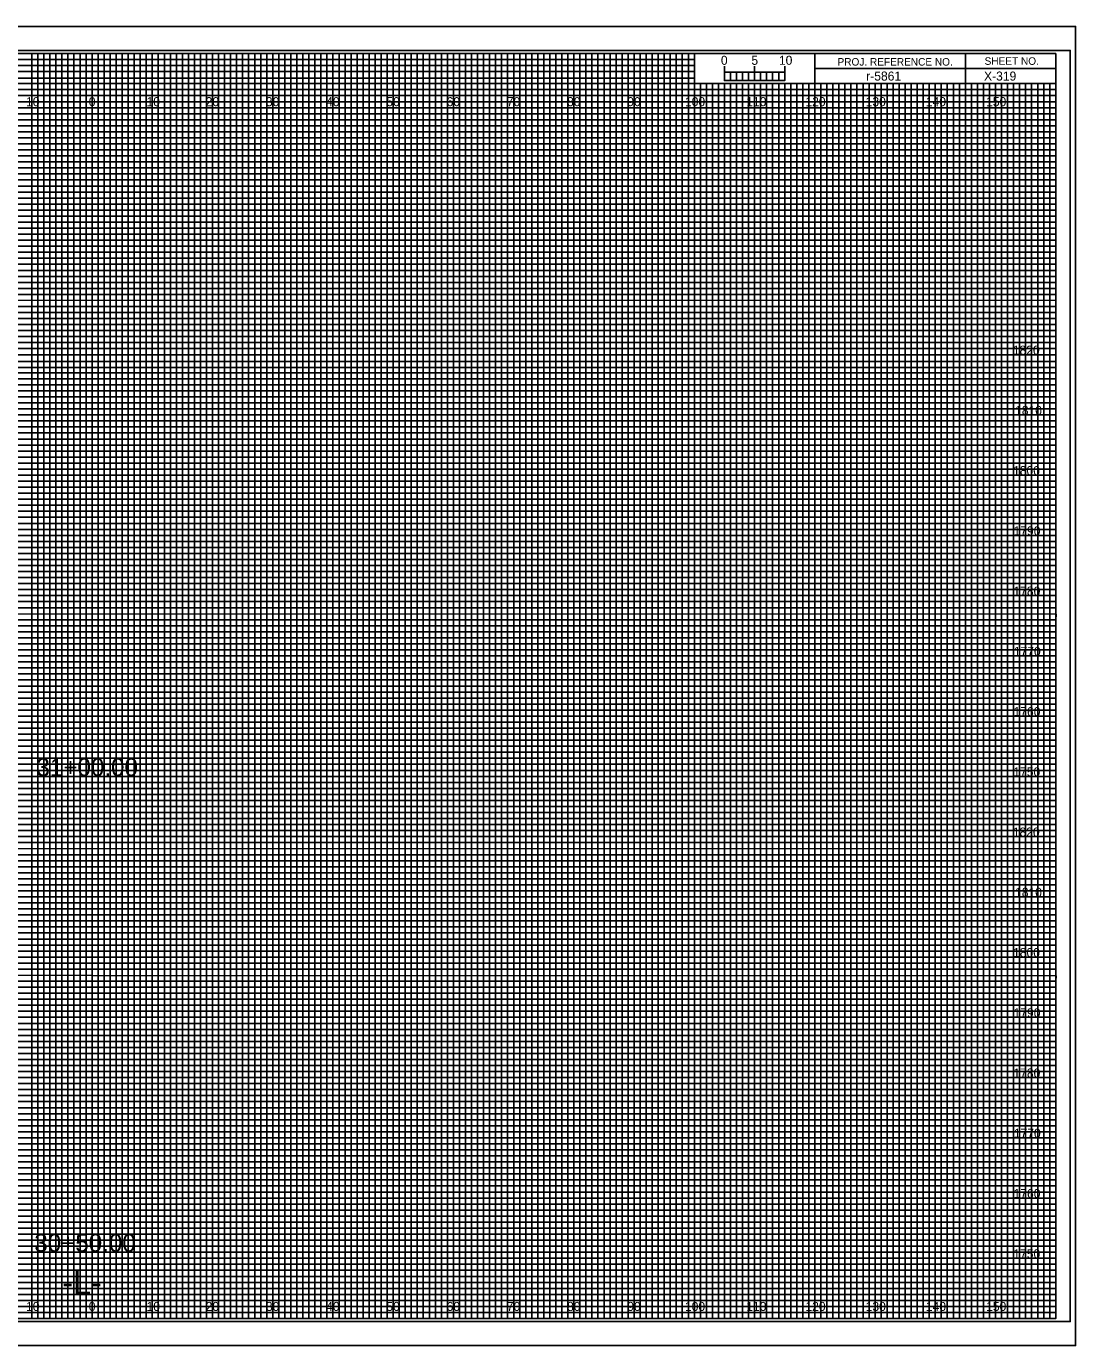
# Model space of a CAD drawing. Extents: x -15 to 323, y -5 to 6170.
# Drawn here: x 149.1 to 323.3, y 3295.5 to 3514.5 of the extents above; entities that cross this region are included whole.
import ezdxf

# ---------------------------------------------------------------- set-up
doc = ezdxf.new("R2010")
doc.units = 0
for name, color, linetype in [('Prop XS Alignment Label', 7, 'Continuous'), ('Prop XS Bar Scale Labels', 7, 'Continuous'), ('Prop XS DDE', 7, 'Continuous'), ('Prop XS DDE Earthwork Shape', 7, 'Continuous'), ('Prop XS DDE Slope Text', 7, 'Continuous'), ('Prop XS DDE Text', 7, 'Continuous'), ('Prop XS Earthwork Shape', 7, 'Continuous'), ('Prop XS Noise Wall', 7, 'Continuous'), ('Prop XS Project Number', 7, 'Continuous'), ('Prop XS Retaining Wall', 7, 'Continuous'), ('Prop XS Station Labels', 7, 'Continuous'), ('Prop XS Temporary Shoring', 7, 'Continuous'), ('Scratch_Level_3', 7, 'Continuous'), ('Scratch_Level_7', 7, 'Continuous'), ('Scratch_Level_8', 7, 'Continuous'), ('Sheet Cross Section Grid Minor 1 CELL', 7, 'Continuous')]:
    doc.layers.add(name, color=color, linetype=linetype)

msp = doc.modelspace()

# ---------------------------------------------------------------- linework, layer by layer
at = {"layer": 'Prop XS Alignment Label'}
for p, q in [((265, 3505.49), (265, 3507.9)), ((265, 3506.9), (265, 3507.9)), ((270, 3505.49), (270, 3507.9)), ((275, 3505.49), (275, 3507.9)), ((275, 3506.9), (275, 3507.9))]:
    msp.add_line(p, q, dxfattribs=at)
for points in [[(275, 3506.9), (265, 3506.9), (265, 3505.49), (275, 3505.49)], [(265, 3506.9), (266, 3506.9), (266, 3505.49), (265, 3505.49)], [(267, 3506.9), (268, 3506.9), (268, 3505.49), (267, 3505.49)], [(269, 3506.9), (270, 3506.9), (270, 3505.49), (269, 3505.49)], [(271, 3506.9), (272, 3506.9), (272, 3505.49), (271, 3505.49)], [(273, 3506.9), (274, 3506.9), (274, 3505.49), (273, 3505.49)]]:
    msp.add_lwpolyline(points, close=True, dxfattribs=at)
at = {"layer": 'Prop XS DDE'}
msp.add_lwpolyline([(-13.4, 3295.5), (323.3, 3295.5), (323.3, 3514.5), (-13.4, 3514.5)], close=True, dxfattribs=at)
at = {"layer": 'Prop XS DDE Slope Text'}
msp.add_lwpolyline([(-10.8, 3299.5), (322.4, 3299.5), (322.4, 3510.5), (-10.8, 3510.5)], close=True, dxfattribs=at)
at = {"layer": 'Prop XS DDE Text'}
for p, q in [((150, 3300), (150, 3510)), ((160, 3300), (160, 3510)), ((170, 3300), (170, 3510)), ((180, 3300), (180, 3510)), ((190, 3300), (190, 3510)), ((200, 3300), (200, 3510)), ((210, 3300), (210, 3510)), ((220, 3300), (220, 3510)), ((230, 3300), (230, 3510)), ((240, 3300), (240, 3510)), ((250, 3300), (250, 3510)), ((260, 3300), (260, 3504.69)), ((270, 3300), (270, 3504.69)), ((280, 3300), (280, 3504.69)), ((290, 3300), (290, 3504.69)), ((300, 3300), (300, 3504.69)), ((310, 3300), (310, 3504.69)), ((0, 3500), (320, 3500)), ((0, 3490), (320, 3490)), ((0, 3480), (320, 3480)), ((0, 3470), (320, 3470)), ((0, 3460), (320, 3460)), ((0, 3450), (320, 3450)), ((0, 3440), (320, 3440)), ((0, 3430), (320, 3430)), ((0, 3420), (320, 3420)), ((0, 3410), (320, 3410)), ((0, 3400), (320, 3400)), ((0, 3390), (320, 3390)), ((0, 3380), (320, 3380)), ((0, 3370), (320, 3370)), ((0, 3360), (320, 3360)), ((0, 3350), (320, 3350)), ((0, 3340), (320, 3340)), ((0, 3330), (320, 3330)), ((0, 3320), (320, 3320)), ((0, 3310), (320, 3310))]:
    msp.add_line(p, q, dxfattribs=at)
at = {"layer": 'Prop XS Earthwork Shape'}
for p, q in [((150, 3510), (140, 3510)), ((150, 3300), (150, 3510)), ((170, 3510), (160, 3510)), ((160, 3510), (160, 3300)), ((170, 3300), (170, 3510)), ((190, 3510), (180, 3510)), ((180, 3510), (180, 3300)), ((190, 3300), (190, 3510)), ((210, 3510), (200, 3510)), ((200, 3510), (200, 3300)), ((210, 3300), (210, 3510)), ((230, 3510), (220, 3510)), ((220, 3510), (220, 3300)), ((230, 3300), (230, 3510)), ((250, 3510), (240, 3510)), ((240, 3510), (240, 3300)), ((250, 3300), (250, 3510)), ((260, 3510), (260, 3300)), ((270, 3300), (270, 3505)), ((290, 3505), (280, 3505)), ((280, 3505), (280, 3300)), ((290, 3300), (290, 3505)), ((310, 3505), (300, 3505)), ((300, 3505), (300, 3300)), ((310, 3300), (310, 3505)), ((160, 3300), (150, 3300)), ((180, 3300), (170, 3300)), ((200, 3300), (190, 3300)), ((220, 3300), (210, 3300)), ((240, 3300), (230, 3300)), ((260, 3300), (250, 3300)), ((280, 3300), (270, 3300)), ((300, 3300), (290, 3300)), ((320, 3300), (310, 3300)), ((320, 3300), (320, 3300))]:
    msp.add_line(p, q, dxfattribs=at)
for points in [[(0, 3500), (320, 3500), (320, 3490), (0, 3490)], [(0, 3480), (320, 3480), (320, 3470), (0, 3470)], [(0, 3460), (320, 3460), (320, 3450), (0, 3450)], [(0, 3440), (320, 3440), (320, 3430), (0, 3430)], [(0, 3420), (320, 3420), (320, 3410), (0, 3410)], [(0, 3400), (320, 3400), (320, 3390), (0, 3390)], [(0, 3380), (320, 3380), (320, 3370), (0, 3370)], [(0, 3360), (320, 3360), (320, 3350), (0, 3350)], [(0, 3340), (320, 3340), (320, 3330), (0, 3330)], [(0, 3320), (320, 3320), (320, 3310), (0, 3310)]]:
    msp.add_lwpolyline(points, dxfattribs=at)
at = {"layer": 'Prop XS Noise Wall'}
for p, q in [((305, 3510), (305, 3505)), ((305, 3505), (305, 3510)), ((280, 3507.5), (280, 3505)), ((320, 3507.49), (280, 3507.49)), ((280, 3505), (320, 3505))]:
    msp.add_line(p, q, dxfattribs=at)
for points in [[(320, 3510), (0, 3510), (0, 3300), (320, 3300)], [(280, 3510), (260, 3510), (260, 3505.03), (280, 3505.03)], [(320, 3510), (280, 3510), (280, 3505), (320, 3505)]]:
    msp.add_lwpolyline(points, close=True, dxfattribs=at)
at = {"layer": 'Prop XS Retaining Wall'}
for p, q in [((267, 3505), (266.01, 3505)), ((266.01, 3505), (266.01, 3300)), ((267, 3300), (267, 3505)), ((269, 3505), (268, 3505)), ((268, 3505), (268, 3300)), ((269, 3300), (269, 3505)), ((266.01, 3300), (265, 3300)), ((268, 3300), (267, 3300))]:
    msp.add_line(p, q, dxfattribs=at)
for points in [[(150, 3300), (151, 3300), (151, 3510), (152, 3510), (152, 3300)], [(152, 3300), (153, 3300), (153, 3510), (154, 3510), (154, 3300)], [(155, 3300), (156, 3300), (156, 3510), (157, 3510), (157, 3300)], [(157, 3300), (158, 3300), (158, 3510), (159, 3510), (159, 3300)], [(160, 3300), (161, 3300), (161, 3510), (162, 3510), (162, 3300)], [(162, 3300), (163, 3300), (163, 3510), (164, 3510), (164, 3300)], [(165, 3300), (166, 3300), (166, 3510), (167, 3510), (167, 3300)], [(167, 3300), (168, 3300), (168, 3510), (169, 3510), (169, 3300)], [(170, 3300), (171, 3300), (171, 3510), (172, 3510), (172, 3300)], [(172, 3300), (173, 3300), (173, 3510), (174, 3510), (174, 3300)], [(175, 3300), (176, 3300), (176, 3510), (177, 3510), (177, 3300)], [(177, 3300), (178, 3300), (178, 3510), (179, 3510), (179, 3300)], [(180, 3300), (181, 3300), (181, 3510), (182, 3510), (182, 3300)], [(182, 3300), (183, 3300), (183, 3510), (184, 3510), (184, 3300)], [(185, 3300), (186, 3300), (186, 3510), (187, 3510), (187, 3300)], [(187, 3300), (188, 3300), (188, 3510), (189, 3510), (189, 3300)], [(190, 3300), (191, 3300), (191, 3510), (192, 3510), (192, 3300)], [(192, 3300), (193, 3300), (193, 3510), (194, 3510), (194, 3300)], [(195, 3300), (196, 3300), (196, 3510), (197, 3510), (197, 3300)], [(197, 3300), (198, 3300), (198, 3510), (199, 3510), (199, 3300)], [(200, 3300), (201, 3300), (201, 3510), (202, 3510), (202, 3300)], [(202, 3300), (203, 3300), (203, 3510), (204, 3510), (204, 3300)], [(205, 3300), (206, 3300), (206, 3510), (207, 3510), (207, 3300)], [(207, 3300), (208, 3300), (208, 3510), (209, 3510), (209, 3300)], [(210, 3300), (211, 3300), (211, 3510), (212, 3510), (212, 3300)], [(212, 3300), (213, 3300), (213, 3510), (214, 3510), (214, 3300)], [(215, 3300), (216, 3300), (216, 3510), (217, 3510), (217, 3300)], [(217, 3300), (218, 3300), (218, 3510), (219, 3510), (219, 3300)], [(220, 3300), (221, 3300), (221, 3510), (222, 3510), (222, 3300)], [(222, 3300), (223, 3300), (223, 3510), (224, 3510), (224, 3300)], [(225, 3300), (226, 3300), (226, 3510), (227, 3510), (227, 3300)], [(227, 3300), (228, 3300), (228, 3510), (229, 3510), (229, 3300)], [(230, 3300), (231, 3300), (231, 3510), (232, 3510), (232, 3300)], [(232, 3300), (233, 3300), (233, 3510), (234, 3510), (234, 3300)], [(235, 3300), (236, 3300), (236, 3510), (237, 3510), (237, 3300)], [(237, 3300), (238, 3300), (238, 3510), (239, 3510), (239, 3300)], [(240, 3300), (241, 3300), (241, 3510), (242, 3510), (242, 3300)], [(242, 3300), (243, 3300), (243, 3510), (244, 3510), (244, 3300)], [(245, 3300), (246, 3300), (246, 3510), (247, 3510), (247, 3300)], [(247, 3300), (248, 3300), (248, 3510), (249, 3510), (249, 3300)], [(250, 3300), (251, 3300), (251, 3510), (252, 3510), (252, 3300)], [(252, 3300), (253, 3300), (253, 3510), (254, 3510), (254, 3300)], [(255, 3300), (256, 3300), (256, 3510), (257, 3510), (257, 3300)], [(257, 3300), (258, 3300), (258, 3510), (259, 3510), (259, 3300)], [(260, 3300), (261, 3300), (261, 3505), (262.02, 3505), (262.02, 3300)], [(262, 3300), (263, 3300), (263, 3505), (263.99, 3505), (263.99, 3300)], [(270, 3300), (270.98, 3300), (270.98, 3505), (272, 3505), (272, 3300)], [(272, 3300), (273, 3300), (273, 3505), (274.05, 3505), (274.05, 3300)], [(275, 3300), (276, 3300), (276, 3505), (277, 3505), (277, 3300)], [(277, 3300), (278, 3300), (278, 3505), (279, 3505), (279, 3300)], [(280, 3300), (281, 3300), (281, 3505), (282, 3505), (282, 3300)], [(282, 3300), (283, 3300), (283, 3505), (284, 3505), (284, 3300)], [(285, 3300), (286, 3300), (286, 3505), (287, 3505), (287, 3300)], [(287, 3300), (288, 3300), (288, 3505), (289, 3505), (289, 3300)], [(290, 3300), (291, 3300), (291, 3505), (292, 3505), (292, 3300)], [(292, 3300), (293, 3300), (293, 3505), (294, 3505), (294, 3300)], [(295, 3300), (296, 3300), (296, 3505), (297, 3505), (297, 3300)], [(297, 3300), (298, 3300), (298, 3505), (299, 3505), (299, 3300)], [(300, 3300), (301, 3300), (301, 3505), (302, 3505), (302, 3300)], [(302, 3300), (303, 3300), (303, 3505), (304, 3505), (304, 3300)], [(305, 3300), (306, 3300), (306, 3505), (307, 3505), (307, 3300)], [(307, 3300), (308, 3300), (308, 3505), (309, 3505), (309, 3300)], [(310, 3300), (311, 3300), (311, 3505), (312, 3505), (312, 3300)], [(312, 3300), (313, 3300), (313, 3505), (314, 3505), (314, 3300)], [(315, 3300), (316, 3300), (316, 3505), (317, 3505), (317, 3300)], [(317, 3300), (318, 3300), (318, 3505), (319, 3505), (319, 3300)]]:
    msp.add_lwpolyline(points, dxfattribs=at)
at = {"layer": 'Prop XS Station Labels'}
for points in [[(145, 3300), (155, 3300), (155, 3510), (165, 3510), (165, 3300), (175, 3300), (175, 3510), (185, 3510), (185, 3300), (195, 3300), (195, 3510), (205, 3510), (205, 3300), (215, 3300), (215, 3510), (225, 3510), (225, 3300), (235, 3300), (235, 3510), (245, 3510), (245, 3300), (255, 3300), (255, 3510), (259.93, 3510), (260, 3510), (260, 3505), (264.99, 3505), (264.99, 3300), (275, 3300), (275, 3505), (285, 3505), (285, 3300), (295, 3300), (295, 3505), (305, 3505), (305, 3300), (315, 3300), (315, 3505)], [(0, 3505), (275, 3505)], [(0, 3485), (320, 3485), (320, 3495), (0, 3495)], [(0, 3465), (320, 3465), (320, 3475), (0, 3475)], [(0, 3445), (320, 3445), (320, 3455), (0, 3455)], [(0, 3425), (320, 3425), (320, 3435), (0, 3435)], [(0, 3405), (320, 3405), (320, 3415), (0, 3415)], [(0, 3385), (320, 3385), (320, 3395), (0, 3395)], [(0, 3365), (320, 3365), (320, 3375), (0, 3375)], [(0, 3345), (320, 3345), (320, 3355), (0, 3355)], [(0, 3325), (320, 3325), (320, 3335), (0, 3335)], [(0, 3305), (320, 3305), (320, 3315), (0, 3315)]]:
    msp.add_lwpolyline(points, dxfattribs=at)
at = {"layer": 'Scratch_Level_7'}
for p, q in [((323.3, 3514.5), (-13.4, 3514.5)), ((-13.4, 3295.5), (323.3, 3295.5))]:
    msp.add_line(p, q, dxfattribs=at)
at = {"layer": 'Sheet Cross Section Grid Minor 1 CELL'}
for p, q in [((0, 3509), (260, 3509)), ((260, 3509), (260, 3507.98)), ((260, 3507.98), (0, 3507.98)), ((0, 3507), (260, 3507)), ((260, 3507), (260, 3505.89)), ((260, 3505.89), (0, 3505.89)), ((0, 3504), (320, 3504))]:
    msp.add_line(p, q, dxfattribs=at)
for points in [[(0, 3503), (270, 3503), (320, 3503), (320, 3502), (0, 3502)], [(0, 3501), (320, 3501), (320, 3499), (0, 3499)], [(0, 3498), (320, 3498), (320, 3497), (0, 3496.98)], [(0, 3496), (320, 3496), (320, 3494), (0, 3494)], [(0, 3493), (320, 3493), (320, 3492), (0, 3492)], [(0, 3491), (320, 3491), (320, 3489), (0, 3489)], [(0, 3488), (320, 3488), (320, 3487), (0, 3487)], [(0, 3486), (320, 3486), (320, 3484), (0, 3484)], [(0, 3483), (320, 3483), (320, 3482), (0, 3482)], [(0, 3481), (320, 3481), (320, 3479), (0, 3479)], [(0, 3478), (320, 3478), (320, 3477), (0, 3477)], [(0, 3476), (320, 3476), (320, 3473.95), (320, 3473), (320, 3472), (0, 3472)], [(0, 3474), (320, 3474), (320, 3473), (0, 3473)], [(0, 3471), (320, 3471), (320, 3469), (0, 3469.03)], [(0, 3469.03), (320, 3469), (320, 3468), (0, 3468)], [(0, 3467), (320, 3467), (320, 3466), (0, 3466)], [(0, 3464), (320, 3464), (320, 3463), (0, 3463)], [(0, 3462), (320, 3462), (320, 3461), (0, 3461)], [(-0.07, 3458.89), (320, 3458.89), (320, 3457.88), (-0.07, 3457.88)], [(0, 3457), (320, 3457), (320, 3456), (0, 3456)], [(0, 3454), (320, 3454), (320, 3453), (0, 3453)], [(0, 3452), (320, 3452), (320, 3451), (0, 3451)], [(0, 3449), (320, 3449), (320, 3448), (0, 3448)], [(0, 3447), (320, 3447), (320, 3446), (0, 3446)], [(0, 3444), (320, 3444), (320, 3443), (0, 3443)], [(0, 3442), (320, 3442), (320, 3441), (0, 3441)], [(0, 3439), (320, 3439), (319.99, 3437.98), (0, 3438)], [(0, 3437), (320, 3437), (320, 3436), (0, 3436)], [(0, 3434), (320, 3434), (320, 3433), (0, 3433)], [(0, 3432), (320, 3432), (320, 3431), (0, 3431)], [(0, 3429), (320, 3429), (320, 3428), (0, 3428)], [(0, 3427), (320, 3427), (320, 3426), (0, 3426)], [(0, 3424), (320, 3424), (320, 3423), (0, 3423)], [(0, 3422), (320, 3422), (320, 3421), (0, 3421)], [(0, 3419), (320, 3419), (320, 3418), (0, 3418)], [(0, 3416.99), (320.07, 3416.91), (320, 3416), (0, 3416)], [(0, 3414), (320, 3414), (320, 3413), (0, 3413)], [(0, 3412), (320, 3412), (320, 3411), (0, 3411)], [(0, 3409), (320, 3409), (320, 3408), (0, 3408)], [(0, 3407), (320, 3407), (320, 3406), (0, 3406)], [(0, 3404), (320, 3404), (320, 3403), (0, 3403)], [(0, 3402), (320, 3402), (320, 3401), (0, 3401)], [(0, 3399), (320, 3399), (320, 3398), (0, 3398)], [(0, 3397), (320, 3397), (320, 3396), (0, 3396)], [(0, 3394), (320, 3394), (320, 3393), (0, 3393)], [(0, 3392), (320, 3392), (320, 3391), (0, 3391)], [(0, 3389), (320, 3389), (320, 3388), (0, 3388)], [(0, 3387), (320, 3387), (320, 3386), (0, 3386)], [(0, 3384), (320, 3384), (320, 3383), (0, 3383)], [(0, 3382), (320, 3382), (320, 3381), (0, 3381)], [(0, 3379), (320, 3379), (319.99, 3377.98), (0, 3378)], [(0, 3377), (320, 3377), (320, 3376), (0, 3376)], [(0, 3374), (320, 3374), (320, 3373), (0, 3373)], [(0, 3372), (320, 3372), (320, 3371), (0, 3371)], [(0, 3369), (320, 3369), (320, 3368), (0, 3368)], [(0, 3367), (320, 3367), (320, 3366), (0, 3366)], [(0, 3364), (320, 3364), (320, 3363), (0, 3363)], [(0, 3362), (320, 3362), (320, 3361), (0, 3361)], [(0, 3359), (320, 3359), (320, 3358), (0, 3358)], [(0, 3356.99), (320.07, 3356.91), (320, 3356), (0, 3356)], [(0, 3354), (320, 3354), (320, 3353), (0, 3353)], [(0, 3352), (320, 3352), (320, 3351), (0, 3351)], [(0, 3349), (320, 3349), (320, 3348), (0, 3348)], [(0, 3347), (320, 3347), (320, 3346), (0, 3346)], [(0, 3344), (320, 3344), (320, 3343), (0, 3343)], [(0, 3342), (320, 3342), (320, 3341), (0, 3341)], [(0, 3339), (320, 3339), (320, 3338), (0, 3338)], [(0, 3337), (320, 3337), (320, 3336), (0, 3336)], [(0, 3334), (320, 3334), (320, 3333), (0, 3333)], [(0, 3332), (320, 3332), (320, 3331), (0, 3331)], [(0, 3329), (320, 3329), (320, 3328), (0, 3328)], [(0, 3327), (320, 3327), (320, 3326), (0, 3326)], [(0, 3324), (320, 3324), (320, 3323), (0, 3323)], [(0, 3322), (320, 3322), (320, 3321), (0, 3321)], [(0, 3319), (320, 3319), (320, 3318), (0, 3318)], [(0, 3317), (320, 3317), (320, 3316), (0, 3316)], [(0, 3314), (320, 3314), (320, 3313), (0, 3313)], [(0, 3312), (320, 3312), (320, 3311), (0, 3311)], [(0, 3309), (320, 3309), (320, 3308), (0, 3308)], [(0, 3307), (320, 3307), (320, 3306), (0, 3306)], [(0, 3304), (320, 3304), (320, 3303), (0, 3303)], [(0, 3302), (320, 3302), (320, 3301), (0, 3301)]]:
    msp.add_lwpolyline(points, dxfattribs=at)

# ---------------------------------------------------------------- texts
at = {"layer": 'Prop XS Alignment Label'}
for s, height, p in [('0', 1.5, (264.41, 3508.12)), ('-L-', 4, (155.06, 3304))]:
    msp.add_text(s, height=height, dxfattribs=at).set_placement(p)
at = {"layer": 'Prop XS Bar Scale Labels'}
for s, p in [('5', (269.47, 3508.12)), ('10', (274.04, 3508.12))]:
    msp.add_text(s, height=1.5, dxfattribs=at).set_placement(p)
at = {"layer": 'Prop XS DDE Earthwork Shape'}
msp.add_text('X-319', height=1.5, dxfattribs=at).set_placement((308.09, 3505.5))
at = {"layer": 'Prop XS Noise Wall'}
for s, p in [('PROJ. REFERENCE NO.', (283.77, 3507.99)), ('SHEET NO.', (308.19, 3508.12))]:
    msp.add_text(s, height=1.25, dxfattribs=at).set_placement(p)
at = {"layer": 'Prop XS Project Number'}
msp.add_text('r-5861', height=1.5, dxfattribs=at).set_placement((288.53, 3505.5))
at = {"layer": 'Prop XS Temporary Shoring'}
for s, p in [('31+00.00', (150.77, 3390.03)), ('30+50.00', (150.41, 3311.06))]:
    msp.add_text(s, height=3, dxfattribs=at).set_placement(p)
at = {"layer": 'Scratch_Level_3'}
for s, p in [('1820', (312.87, 3460)), ('1810', (313.25, 3450)), ('1800', (312.92, 3440)), ('1790', (313, 3430)), ('1780', (312.98, 3420)), ('1770', (313.04, 3410)), ('1760', (313, 3400)), ('1750', (312.96, 3390)), ('1820', (312.87, 3380)), ('1810', (313.25, 3370)), ('1800', (312.92, 3360)), ('1790', (313, 3350)), ('1780', (312.98, 3340)), ('1770', (313.04, 3330)), ('1760', (313, 3320)), ('1750', (312.96, 3310))]:
    msp.add_text(s, height=1.5, dxfattribs=at).set_placement(p)
at = {"layer": 'Scratch_Level_8'}
for s, p in [('10', (149.04, 3501.25)), ('0', (159.45, 3501.25)), ('0', (159.45, 3501.25)), ('10', (169.04, 3501.25)), ('20', (178.86, 3501.25)), ('30', (188.86, 3501.25)), ('40', (198.86, 3501.25)), ('50', (208.86, 3501.25)), ('60', (218.86, 3501.25)), ('70', (228.86, 3501.25)), ('80', (238.86, 3501.25)), ('90', (248.86, 3501.25)), ('100', (258.44, 3501.25)), ('110', (268.62, 3501.25)), ('120', (278.44, 3501.25)), ('130', (288.44, 3501.25)), ('140', (298.44, 3501.25)), ('150', (308.44, 3501.25)), ('10', (149.04, 3301.25)), ('0', (159.45, 3301.25)), ('0', (159.45, 3301.25)), ('10', (169.04, 3301.25)), ('20', (178.86, 3301.25)), ('30', (188.86, 3301.25)), ('40', (198.86, 3301.25)), ('50', (208.86, 3301.25)), ('60', (218.86, 3301.25)), ('70', (228.86, 3301.25)), ('80', (238.86, 3301.25)), ('90', (248.86, 3301.25)), ('100', (258.44, 3301.25)), ('110', (268.62, 3301.25)), ('120', (278.44, 3301.25)), ('130', (288.44, 3301.25)), ('140', (298.44, 3301.25)), ('150', (308.44, 3301.25))]:
    msp.add_text(s, height=1.5, dxfattribs=at).set_placement(p)

doc.saveas('drawing.dxf')
